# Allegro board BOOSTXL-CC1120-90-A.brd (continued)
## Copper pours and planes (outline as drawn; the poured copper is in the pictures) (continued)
Net_5 on BOTTOM (solid shape): 112.96,19.41 113.66,19.41 113.66,18.7 112.65,17.69 112.49,17.58 112.3,17.54 109.5,17.54 108.66,16.7 107.96,16.7 107.96,17.41 108.94,18.39 109.11,18.5 109.3,18.54 112.09,18.54
Net_6 on BOTTOM (solid shape): 112.96,17.41 113.66,17.41 113.66,16.7 112.65,15.69 112.49,15.58 112.3,15.54 109.5,15.54 108.66,14.7 107.96,14.7 107.96,15.41 108.94,16.39 109.11,16.5 109.3,16.54 112.09,16.54
Net_7 on BOTTOM (solid shape): 112.96,15.41 113.66,15.41 113.66,14.7 112.65,13.69 112.49,13.58 112.3,13.54 109.5,13.54 108.66,12.7 107.96,12.7 107.96,13.41 108.94,14.39 109.11,14.5 109.3,14.54 112.09,14.54
Net_8 on BOTTOM (solid shape): 112.96,13.41 113.66,13.41 113.66,12.7 112.65,11.69 112.49,11.58 112.3,11.54 109.5,11.54 108.66,10.7 107.96,10.7 107.96,11.41 108.94,12.39 109.11,12.5 109.3,12.54 112.09,12.54
Net_9 on BOTTOM (solid shape): 112.96,11.41 113.66,11.41 113.66,10.7 112.65,9.68 112.49,9.58 112.3,9.54 109.5,9.54 108.66,8.7 107.96,8.7 107.96,9.41 108.94,10.39 109.11,10.5 109.3,10.54 112.09,10.54
Net_10 on BOTTOM (solid shape): 112.96,9.41 113.66,9.41 113.66,8.7 112.65,7.68 112.49,7.58 112.3,7.54 109.5,7.54 108.66,6.7 107.96,6.7 107.96,7.41 108.94,8.39 109.11,8.5 109.3,8.54 112.09,8.54
Net_11 on BOTTOM (solid shape): 112.96,27.4 113.66,27.4 113.66,26.7 112.65,25.68 112.49,25.58 112.3,25.54 109.5,25.54 108.66,24.7 107.96,24.7 107.96,25.41 108.94,26.39 109.11,26.5 109.3,26.54 112.09,26.54

Small or netless copper shapes (teardrops, artwork), in the pictures only: 14 on TOP

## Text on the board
BOTTOM: 4 | Bottom Layer
Ref Des/Assembly Bottom: 2 | Assembly-Bottom
Board Geometry/Soldermask Bottom: 6 | Soldermask-Bottom
Package Geometry/Pastemask Bottom: 10 | Pastemask-Bottom
Ref Des/Silkscreen Bottom: Refer to an AppNote-AN136 | SmartRFStudio Mode: | MSP430 LaunchPad Mode: | 8 | Silkscreen-Bottom | For evaluation only; | not FCC approved for resale
User.Comments: Note:Connectors P2 and P3 should be mounted from the Bottom side.The pins of the connectors should appear on the TOP side
TOP: 1 | Top Layer
Ref Des/Assembly Top: 1 | 2 | Assembly-Top
Board Geometry/Soldermask Top: 5 | Soldermask-Top
Package Geometry/Pastemask Top: 9 | Pastemask- Top
Ref Des/Silkscreen Top: LNA_EN | PA_EN | SCLK | GND | 5V | USB Ready | GPIO0 | GPIO3 | CS_N | RESET | GPIO2 | MISO | MOSI | BOOSTXL-CC1120-90 | REV-A | 2 | 1 | 11 | 12 | 3 | 7 | Silkscreen-Top
LAYER2: 2 | Layer-2
LAYER3: 3 | Layer-3
XSECTION_CHART: *  SURFACE - AIR 0 MIL | L1: TOP CONDUCTOR - COPPER 1.4 MIL | *  DIELECTRIC - FR-4 15.7 MIL | L2: LAYER2 CONDUCTOR - COPPER 1.4 MIL | *  DIELECTRIC - FR-4 11.8 MIL | L3: LAYER3 CONDUCTOR - COPPER 1.4 MIL | L4: BOTTOM CONDUCTOR - COPPER 1.4 MIL | DESIGN CROSS SECTION CHART | ___________________________ | TOTAL THICKNESS 48.8 MIL | 1-4
DIMENSION: FAB NOTES: | 1. ALL DIMENSIONS ARE IN INCHES, UNLESS OTHERWISE NOTED. | 2. THE PWB SHALL BE FABRICATED TO IPC-6012, CLASS 2 AND WORKMANSHIP SHALL CONFORM TO IPC-A-600, CLASS 2. CURRENT REVISIONS. | 3. BOARD MATERIAL SHALL BE 180 Tg/340 Td ISOLA FR-370HR OR EQUIVALENT, RoHS COMPLIANT AND LEAD FREE ASSEMBLY CAPABLE. BOARD MATERIAL SHALL MEET OR EXCEED IPC-4101B. RoHS CERTIFICATE OF CONFORMANCE SHALL BE DELIVERED WITH EACH LOT. | 4. BOARD MATERIAL & CONSTRUCTION TO BE U.L. 94V-0 APPROVED. UL LOGO, UL RATING AND UL GUIDE NUMBER SHOULD BE MARKED ON THE FINISHED BOARD. | 5. OVERALL BOARD THICKNESS TO BE .049 +/-.005" AND APPLIES AFTER ALL LAMINATION AND PLATING PROCESSES, MEASURED FROM COPPER TO COPPER. | 6. MAX. WARP & TWIST TO BE .0075 PER INCH. | 7. BOARD MUST BE ELECTRICALLY TESTED USING SUPPLIED IPC-D-356 NETLIST. | 8. 28 MIL TRACES ON LAYER 1 ARE 50 OHMS +/-10%. THEY ARE REFERENCE TO LAYER 2 GROUND. | PROCESS NOTES: | 1. APPLY LPI SOLDERMASK OVER BARE COPPER (SMOBC), SOLDERMASK SHALL CONFORM TO IPC-SM-840. CLASS H. CURRENT REV. COLOR OF MASK TO BE RED. | 2. PLATE ALL EXPOSED AREAS WITH ELECTROLESS NICKEL  IMMERSION GOLD.   NICKEL: 100 MICRO-INCHES MIN. GOLD: 2-8 MICROINCHES MIN. | 3. SOLDERMASK ARTWORK HAS ZERO (0) OVERSIZED PADS. FABRICATION VENDOR IS ALLOWED TO ADJUST THE COMPONENT SOLDERMASK PADS TO MEET THEIR TOOLING REQUIREMENTS. | 4. APPLY NON-CONDUCTIVE LPI SILKSCREEN OR EQUIVALENT PER THE ARTWORK. COLOR: WHITE. | 5. ALL VIAS ARE TENTED | 1 | Fabrication Drawing
User.5: FIGURE | SIZE | 8.0 | 10.0 | 15.0 | 15.75 | 20.0 | 30.0 | 41.34 | DRILL CHART: TOP to BOTTOM | ALL UNITS ARE IN MILS | TOLERANCE | +3.0/-3.0 | PLATED | QTY | 2 | 672 | 14 | 21 | 1 | 8 | 10 | 40
